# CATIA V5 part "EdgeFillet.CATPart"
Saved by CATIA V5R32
Part number: Part1
Bounding box of the stored display mesh (mm): x -55 to 55, y -155 to 25.782, z -44.572 to 40
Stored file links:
  D:\PROJECTS\Project 2022\CATIA V5 6R 2022\Resources\Part Files\c17_catia_v6_6r2022_prt\EdgeFillet.CATPart
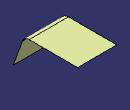
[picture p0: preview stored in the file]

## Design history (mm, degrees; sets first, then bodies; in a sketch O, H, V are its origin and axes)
Body1 (main body)
  Sketch1 on yz-plane, origin (0, 0, 0), H (0, 1, 0), V (0, 0, 1)
    point P1 (25.7818, 40)
    line L1 (25.7818, 40) -> (-124.2182, 40)
    line L2 (-124.2182, 40) -> (-155, -44.5723)
    point P3 (-155, -44.5723)
    length L1 = 150
    length L2 = 90
    angle L2 L1 = 110
    distance P1 H = 40
    distance P3 V = 155
    horizontal: L1 H
  Extrude1: Element1 Sketch1, Lim1 55, Lim2 55
  Fillet1: radius 20, on edge [face of Extrude1 from Sketch1.L1 | face of Extrude1 from Sketch1.L2]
